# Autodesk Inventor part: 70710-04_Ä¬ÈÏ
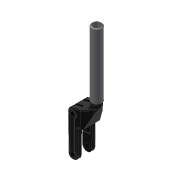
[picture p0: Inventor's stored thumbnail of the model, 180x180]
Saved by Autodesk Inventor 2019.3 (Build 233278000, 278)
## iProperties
Created: 2017-10
Part Number: 70710-04_Ä¬ÈÏ
Material: Ogólny
Document SubType Name: Modeling
Designer: CADENGINEERING4
Density: 1 g/cm^3
Appearance: Domyślna
Author: CADENGINEERING4
Revision Number: ÈÎºÎ
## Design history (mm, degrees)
feature "ÊäÈë1"
feature "ÊäÈë2"
node "Bryła1"
node "Bryła2"
